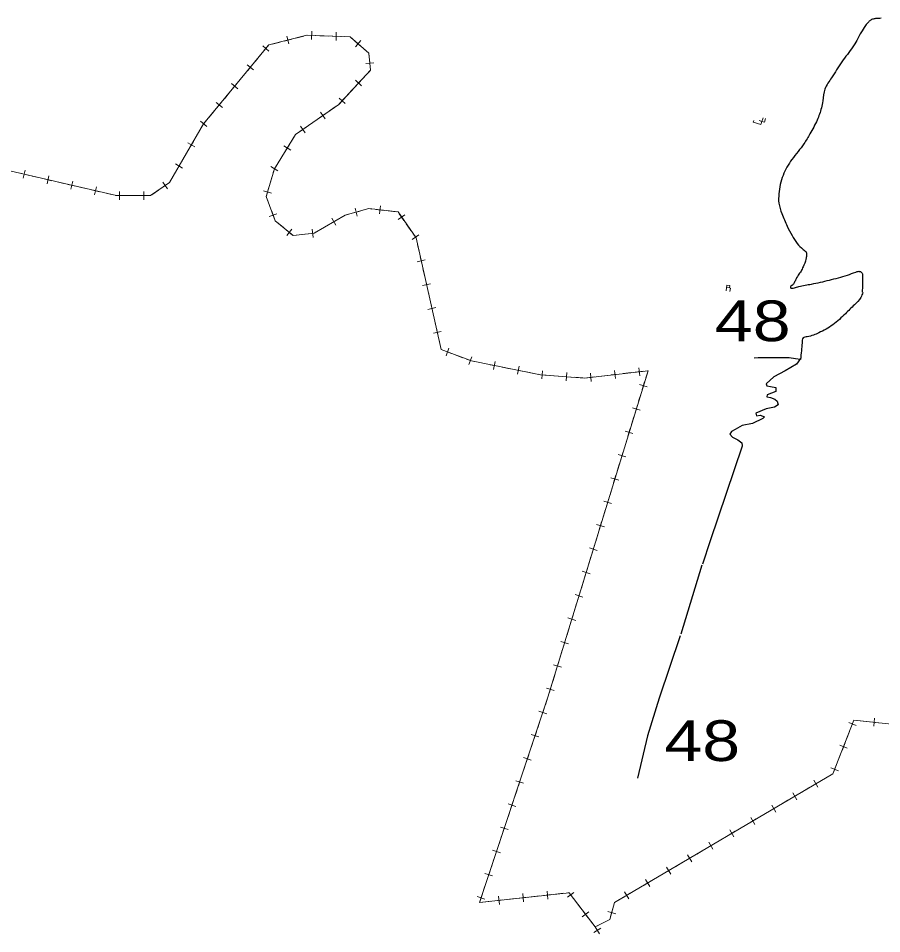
# Model space of a CAD drawing. Extents: x 476989 to 498418, y 4381813 to 4416555.
# Drawn here: x 485556 to 486617, y 4382275 to 4383399 of the extents above; entities that cross this region are included whole.
import ezdxf

# ---------------------------------------------------------------- set-up
doc = ezdxf.new("R2010")
doc.units = 0
doc.header["$LTSCALE"] = 20
doc.linetypes.add('MEDIUM_DASHED', pattern=[4.5, 3, -1.5])
for name, color, linetype, lineweight in [('13', 7, 'Continuous', 13), ('34', 7, 'Continuous', 13), ('48', 7, 'MEDIUM_DASHED', 13), ('6', 7, 'Continuous', 25)]:
    doc.layers.add(name, color=color, linetype=linetype, lineweight=lineweight)

msp = doc.modelspace()

# ---------------------------------------------------------------- linework, layer by layer
at = {"layer": '34'}
for p, q in [((485882.86, 4383370.82), (485892.55, 4383373.29)), ((485886.47, 4383376.9), (485888.94, 4383367.21)), ((485897.4, 4383374.53), (485907.09, 4383377)), ((485911.95, 4383377.96), (485921.94, 4383377.59)), ((485917.13, 4383382.77), (485916.76, 4383372.78)), ((485926.94, 4383377.4), (485936.93, 4383377.02)), ((485941.92, 4383376.83), (485951.91, 4383376.46)), ((485947.1, 4383381.64), (485946.73, 4383371.65)), ((485856.63, 4383364.92), (485864.34, 4383358.56)), ((485857.31, 4383357.88), (485863.67, 4383365.6)), ((485868.34, 4383367.11), (485878.03, 4383369.58)), ((485969.96, 4383370.82), (485977.5, 4383364.26)), ((485977.01, 4383371.31), (485970.45, 4383363.77)), ((485847.77, 4383346.32), (485854.13, 4383354.03)), ((485837.55, 4383341.78), (485845.26, 4383335.42)), ((485838.22, 4383334.75), (485844.59, 4383342.46)), ((485993.15, 4383344.13), (485983.2, 4383343.18)), ((485987.7, 4383348.63), (485988.65, 4383338.68)), ((485828.69, 4383323.18), (485835.05, 4383330.9)), ((485988.11, 4383334.04), (485981.31, 4383326.71)), ((485818.47, 4383318.65), (485826.18, 4383312.29)), ((485819.14, 4383311.61), (485825.5, 4383319.32)), ((485978.17, 4383315.99), (485970.84, 4383322.8)), ((485977.91, 4383323.06), (485971.11, 4383315.73)), ((485809.6, 4383300.05), (485815.97, 4383307.76)), ((485967.7, 4383312.07), (485960.9, 4383304.74)), ((485799.38, 4383295.51), (485807.1, 4383289.15)), ((485800.06, 4383288.47), (485806.42, 4383296.19)), ((485957.76, 4383294.01), (485950.44, 4383300.82)), ((485957.5, 4383301.08), (485950.7, 4383293.75)), ((485790.52, 4383276.91), (485796.89, 4383284.62)), ((485934.45, 4383282.15), (485926.25, 4383276.42)), ((485933.21, 4383275.18), (485927.49, 4383283.38)), ((485946.74, 4383290.73), (485938.54, 4383285)), ((485780.3, 4383272.38), (485788.02, 4383266.01)), ((485922.15, 4383273.56), (485913.95, 4383267.83)), ((485774.05, 4383251.95), (485779.09, 4383260.59)), ((485909.86, 4383264.98), (485901.66, 4383259.25)), ((485908.62, 4383258.02), (485902.9, 4383266.22)), ((485764.7, 4383245.83), (485773.33, 4383240.79)), ((485766.5, 4383238.99), (485771.54, 4383247.63)), ((485891.09, 4383236.95), (485882.59, 4383242.22)), ((485889.47, 4383243.84), (485884.21, 4383235.33)), ((485758.94, 4383226.05), (485763.98, 4383234.68)), ((485881.57, 4383231.08), (485876.31, 4383222.58)), ((485749.59, 4383219.93), (485758.22, 4383214.89)), ((485751.39, 4383213.09), (485756.42, 4383221.73)), ((485875.3, 4383211.45), (485866.8, 4383216.72)), ((485558.85, 4383208.39), (485568.59, 4383206.13)), ((485564.85, 4383212.13), (485562.59, 4383202.39)), ((485573.46, 4383205), (485583.2, 4383202.74)), ((485594.06, 4383205.36), (485591.8, 4383195.61)), ((485743.83, 4383200.14), (485748.87, 4383208.78)), ((485868.21, 4383204.5), (485865.39, 4383194.91)), ((485588.06, 4383201.61), (485597.8, 4383199.36)), ((485602.67, 4383198.23), (485612.42, 4383195.97)), ((485617.28, 4383194.84), (485627.02, 4383192.58)), ((485623.28, 4383198.58), (485621.02, 4383188.84)), ((485732.67, 4383190.51), (485740.88, 4383196.22)), ((485733.92, 4383197.47), (485739.63, 4383189.26)), ((485631.89, 4383191.46), (485641.63, 4383189.2)), ((485646.49, 4383188.07), (485656.23, 4383185.81)), ((485652.49, 4383191.81), (485650.23, 4383182.07)), ((485661.11, 4383184.68), (485670.85, 4383182.43)), ((485680.67, 4383186), (485680.67, 4383176)), ((485690.67, 4383181), (485700.67, 4383181)), ((485705.66, 4383181), (485715.66, 4383181)), ((485710.66, 4383186), (485710.66, 4383176)), ((485720.37, 4383181.95), (485728.58, 4383187.66)), ((485867.36, 4383183.91), (485857.77, 4383186.74)), ((485863.98, 4383190.12), (485861.16, 4383180.53)), ((485862.53, 4383175.82), (485865.97, 4383166.43)), ((485874.11, 4383158.78), (485864.72, 4383155.33)), ((485867.69, 4383161.75), (485871.13, 4383152.36)), ((485966.62, 4383159.38), (485976.26, 4383162.04)), ((485970.11, 4383165.53), (485972.77, 4383155.89)), ((485995.79, 4383164.02), (486005.73, 4383162.92)), ((486001.31, 4383168.44), (486000.21, 4383158.5)), ((486010.7, 4383162.37), (486020.64, 4383161.26)), ((486024.48, 4383158.85), (486030.15, 4383150.61)), ((485873.92, 4383148.43), (485881.66, 4383142.09)), ((485939.78, 4383146.45), (485948.44, 4383151.46)), ((485941.6, 4383153.29), (485946.61, 4383144.63)), ((486031.43, 4383157.56), (486023.19, 4383151.89)), ((485885.53, 4383138.93), (485893.27, 4383132.6)), ((485892.56, 4383139.64), (485886.23, 4383131.9)), ((485917.31, 4383139.72), (485918.46, 4383129.79)), ((485926.81, 4383138.94), (485935.46, 4383143.95)), ((486032.98, 4383146.48), (486038.64, 4383138.24)), ((485898.02, 4383132.46), (485907.96, 4383133.61)), ((486048.42, 4383132.84), (486040.18, 4383127.18)), ((486046.94, 4383120.44), (486049.14, 4383110.69)), ((486056.22, 4383102.05), (486046.47, 4383099.84)), ((486050.24, 4383105.82), (486052.45, 4383096.07)), ((486053.55, 4383091.19), (486055.76, 4383081.44)), ((486062.84, 4383072.8), (486053.09, 4383070.59)), ((486056.86, 4383076.57), (486059.07, 4383066.82)), ((486060.17, 4383061.94), (486062.38, 4383052.19)), ((486063.48, 4383047.32), (486065.69, 4383037.57)), ((486069.46, 4383043.55), (486059.71, 4383041.34)), ((486066.79, 4383032.69), (486069, 4383022.94)), ((486076.08, 4383014.3), (486066.33, 4383012.09)), ((486070.1, 4383018.07), (486072.31, 4383008.32)), ((486073.41, 4383003.44), (486075.62, 4382993.69)), ((486079.05, 4382990.85), (486088.4, 4382987.31)), ((486085.49, 4382993.75), (486081.95, 4382984.4)), ((486093.08, 4382985.54), (486102.43, 4382982)), ((486113.54, 4382983.14), (486110, 4382973.79)), ((486121.52, 4382976.3), (486131.32, 4382974.34)), ((486136.22, 4382973.36), (486146.02, 4382971.4)), ((486142.1, 4382977.28), (486140.14, 4382967.47)), ((486150.93, 4382970.41), (486160.73, 4382968.45)), ((486165.63, 4382967.47), (486175.43, 4382965.51)), ((486171.51, 4382971.4), (486169.55, 4382961.59)), ((486318.77, 4382969.74), (486319.91, 4382959.8)), ((486180.33, 4382964.53), (486190.14, 4382962.57)), ((486200.34, 4382965.84), (486199.6, 4382955.87)), ((486209.94, 4382960.12), (486219.91, 4382959.38)), ((486224.89, 4382959.01), (486234.86, 4382958.27)), ((486230.25, 4382963.63), (486229.51, 4382953.65)), ((486239.85, 4382957.9), (486249.82, 4382957.16)), ((486254.79, 4382957.32), (486264.72, 4382958.47)), ((486259.18, 4382962.86), (486260.33, 4382952.93)), ((486269.69, 4382959.04), (486279.62, 4382960.19)), ((486284.58, 4382960.76), (486294.51, 4382961.91)), ((486288.97, 4382966.3), (486290.12, 4382956.37)), ((486299.48, 4382962.48), (486309.42, 4382963.62)), ((486314.37, 4382964.2), (486324.31, 4382965.34)), ((486329.13, 4382946.12), (486319.57, 4382949.05)), ((486325.82, 4382952.37), (486322.89, 4382942.81)), ((486321.42, 4382938.03), (486318.49, 4382928.47)), ((486317.02, 4382923.7), (486314.09, 4382914.14)), ((486320.34, 4382917.45), (486310.78, 4382920.38)), ((486312.63, 4382909.36), (486309.69, 4382899.8)), ((486311.54, 4382888.78), (486301.98, 4382891.71)), ((486308.23, 4382895.02), (486305.3, 4382885.46)), ((486303.83, 4382880.68), (486300.9, 4382871.12)), ((486299.44, 4382866.35), (486296.5, 4382856.79)), ((486302.75, 4382860.11), (486293.19, 4382863.04)), ((486295.04, 4382852.01), (486292.1, 4382842.45)), ((486293.95, 4382831.44), (486284.39, 4382834.37)), ((486290.64, 4382837.68), (486287.71, 4382828.12)), ((486286.24, 4382823.34), (486283.31, 4382813.78)), ((486285.16, 4382802.76), (486275.6, 4382805.7)), ((486281.85, 4382809.01), (486278.91, 4382799.45)), ((486277.45, 4382794.67), (486274.51, 4382785.11)), ((486276.37, 4382774.09), (486266.81, 4382777.02)), ((486273.05, 4382780.34), (486270.12, 4382770.78)), ((486268.65, 4382766), (486265.72, 4382756.44)), ((486267.57, 4382745.42), (486258.01, 4382748.35)), ((486264.26, 4382751.67), (486261.32, 4382742.11)), ((486259.86, 4382737.33), (486256.93, 4382727.77)), ((486255.46, 4382723), (486252.53, 4382713.44)), ((486251.06, 4382708.65), (486248.13, 4382699.09)), ((486258.78, 4382716.75), (486249.22, 4382719.68)), ((486249.98, 4382688.08), (486240.42, 4382691.01)), ((486246.67, 4382694.32), (486243.74, 4382684.76)), ((486242.27, 4382679.98), (486239.34, 4382670.42)), ((486237.87, 4382665.65), (486234.94, 4382656.09)), ((486241.19, 4382659.41), (486231.63, 4382662.34)), ((486233.47, 4382651.31), (486230.54, 4382641.75)), ((486232.39, 4382630.73), (486222.83, 4382633.67)), ((486229.08, 4382636.98), (486226.15, 4382627.42)), ((486224.68, 4382622.64), (486221.75, 4382613.08)), ((486220.28, 4382608.31), (486217.35, 4382598.75)), ((486223.6, 4382602.06), (486214.04, 4382605)), ((486215.89, 4382593.97), (486212.95, 4382584.41)), ((486214.8, 4382573.39), (486205.24, 4382576.32)), ((486211.49, 4382579.64), (486208.56, 4382570.08)), ((486205.52, 4382544.75), (486196.03, 4382547.91)), ((486202.36, 4382551.07), (486199.2, 4382541.59)), ((486197.61, 4382536.84), (486194.45, 4382527.36)), ((486585.8, 4382530.46), (486576.49, 4382534.13)), ((486582.98, 4382536.94), (486579.31, 4382527.64)), ((486597.84, 4382535.39), (486587.9, 4382536.47)), ((486612.76, 4382533.77), (486602.81, 4382534.85)), ((486607.24, 4382529.34), (486608.33, 4382539.28)), ((486196.04, 4382516.3), (486186.55, 4382519.46)), ((486192.87, 4382522.62), (486189.71, 4382513.14)), ((486577.48, 4382522.99), (486573.82, 4382513.68)), ((486188.13, 4382508.39), (486184.97, 4382498.91)), ((486574.81, 4382502.56), (486565.5, 4382506.22)), ((486571.99, 4382509.04), (486568.32, 4382499.74)), ((486566.49, 4382495.09), (486562.82, 4382485.78)), ((486186.55, 4382487.85), (486177.07, 4382491.01)), ((486183.39, 4382494.17), (486180.23, 4382484.69)), ((486178.65, 4382479.94), (486175.49, 4382470.46)), ((486563.81, 4382474.65), (486554.51, 4382478.32)), ((486560.99, 4382481.14), (486557.33, 4382471.83)), ((486177.07, 4382459.4), (486167.58, 4382462.56)), ((486173.91, 4382465.72), (486170.74, 4382456.23)), ((486540.55, 4382461.3), (486531.94, 4382456.22)), ((486538.79, 4382454.46), (486533.71, 4382463.07)), ((486553.47, 4382468.92), (486544.85, 4382463.84)), ((486169.16, 4382451.49), (486166, 4382442)), ((486527.63, 4382453.69), (486519.02, 4382448.61)), ((486514.72, 4382446.07), (486506.1, 4382440.99)), ((486512.95, 4382439.23), (486507.87, 4382447.84)), ((486167.59, 4382430.95), (486158.1, 4382434.11)), ((486164.42, 4382437.27), (486161.26, 4382427.78)), ((486488.88, 4382430.84), (486480.27, 4382425.76)), ((486487.12, 4382424), (486482.04, 4382432.61)), ((486501.8, 4382438.45), (486493.18, 4382433.38)), ((486159.68, 4382423.04), (486156.52, 4382413.55)), ((486461.28, 4382408.76), (486456.2, 4382417.38)), ((486475.96, 4382423.22), (486467.35, 4382418.15)), ((486158.1, 4382402.49), (486148.62, 4382405.66)), ((486154.94, 4382408.82), (486151.78, 4382399.33)), ((486450.13, 4382407.99), (486441.51, 4382402.91)), ((486463.05, 4382415.61), (486454.43, 4382410.53)), ((486150.2, 4382394.59), (486147.03, 4382385.1)), ((486437.21, 4382400.38), (486428.6, 4382395.3)), ((486435.45, 4382393.53), (486430.37, 4382402.15)), ((486411.38, 4382385.15), (486402.77, 4382380.07)), ((486409.61, 4382378.3), (486404.53, 4382386.92)), ((486424.29, 4382392.76), (486415.68, 4382387.68)), ((486148.62, 4382374.04), (486139.13, 4382377.21)), ((486145.46, 4382380.37), (486142.29, 4382370.88)), ((486383.78, 4382363.07), (486378.7, 4382371.69)), ((486398.46, 4382377.53), (486389.84, 4382372.45)), ((486140.71, 4382366.14), (486137.55, 4382356.65)), ((486372.62, 4382362.3), (486364.01, 4382357.22)), ((486385.55, 4382369.92), (486376.93, 4382364.84)), ((486135.97, 4382351.92), (486132.81, 4382342.43)), ((486359.71, 4382354.69), (486351.1, 4382349.61)), ((486357.94, 4382347.84), (486352.86, 4382356.46)), ((486131.23, 4382337.69), (486128.07, 4382328.2)), ((486139.13, 4382345.59), (486129.65, 4382348.75)), ((486333.88, 4382339.46), (486325.26, 4382334.38)), ((486332.11, 4382332.61), (486327.03, 4382341.23)), ((486346.79, 4382347.07), (486338.18, 4382341.99)), ((486205.9, 4382327.07), (486206.98, 4382317.13)), ((486320.96, 4382331.84), (486312.34, 4382326.76)), ((486129.65, 4382317.14), (486120.16, 4382320.3)), ((486126.49, 4382323.47), (486123.33, 4382313.98)), ((486141.85, 4382315.06), (486151.79, 4382316.14)), ((486146.27, 4382320.57), (486147.36, 4382310.63)), ((486156.76, 4382316.68), (486166.7, 4382317.77)), ((486171.66, 4382318.31), (486181.6, 4382319.39)), ((486176.09, 4382323.82), (486177.17, 4382313.88)), ((486186.57, 4382319.93), (486196.51, 4382321.02)), ((486201.47, 4382321.56), (486211.41, 4382322.65)), ((486216.38, 4382323.19), (486226.32, 4382324.27)), ((486238.96, 4382325.43), (486231.01, 4382319.36)), ((486308.04, 4382324.23), (486299.43, 4382319.15)), ((486306.27, 4382317.38), (486301.2, 4382325.99)), ((486126.94, 4382313.43), (486136.89, 4382314.51)), ((486241.05, 4382314.44), (486247.11, 4382306.49)), ((486286.83, 4382305.42), (486284.09, 4382295.8)), ((486257.14, 4382301.57), (486249.18, 4382295.51)), ((486250.13, 4382302.52), (486256.19, 4382294.56)), ((486290.27, 4382299.24), (486280.65, 4382301.98)), ((486259.22, 4382290.59), (486265, 4382283)), ((486271.92, 4382281.59), (486263.58, 4382276.08)), ((486268.66, 4382284.83), (486265, 4382283)), ((486265, 4382283), (486270.51, 4382274.66)), ((486282.07, 4382291.53), (486273.12, 4382287.06))]:
    msp.add_line(p, q, dxfattribs=at)
for points in [[(485526, 4383216), (485677, 4383181), (485719, 4383181), (485742, 4383197), (485784, 4383269), (485864, 4383366), (485911, 4383378), (485964, 4383376), (485987, 4383356), (485989, 4383335), (485950, 4383293), (485897, 4383256), (485871, 4383214), (485861, 4383180), (485872, 4383150), (485894, 4383132), (485920, 4383135), (485958, 4383157), (485987, 4383165), (486023, 4383161), (486045, 4383129), (486076, 4382992), (486113, 4382978), (486198, 4382961), (486252, 4382957), (486330, 4382966), (486207, 4382565), (486123, 4382313), (486233, 4382325), (486265, 4382283)], [(485956.91, 4383376.27), (485964, 4383376), (485966.19, 4383374.1)], [(485981.27, 4383360.98), (485987, 4383356), (485987.23, 4383353.6)], [(487676.62, 4383311.4), (487577, 4383232), (487304, 4383028), (487077, 4382869), (487054, 4382844), (487031, 4382851), (487023, 4382817), (486778, 4382653), (486740, 4382634), (486629, 4382532), (486583, 4382537), (486557, 4382471), (486289, 4382313), (486283, 4382292), (486265, 4382283)], [(485781.61, 4383264.9), (485784, 4383269), (485787.34, 4383273.05)], [(485897.56, 4383256.39), (485897, 4383256), (485892.1, 4383248.08)], [(485873.68, 4383218.34), (485871, 4383214), (485869.62, 4383209.3)], [(485675.71, 4383181.3), (485677, 4383181), (485685.67, 4383181)], [(485981.08, 4383163.37), (485987, 4383165), (485990.83, 4383164.57)], [(485952.76, 4383153.97), (485958, 4383157), (485961.81, 4383158.05)], [(485912.92, 4383134.18), (485920, 4383135), (485922.48, 4383136.44)], [(486041.47, 4383134.13), (486045, 4383129), (486045.83, 4383125.32)], [(486107.1, 4382980.23), (486113, 4382978), (486116.62, 4382977.28)], [(486195.03, 4382961.59), (486198, 4382961), (486204.96, 4382960.48)], [(486329.27, 4382965.92), (486330, 4382966), (486327.28, 4382957.14)], [(486207.09, 4382565.3), (486207, 4382565), (486203.94, 4382555.81)], [(486231.29, 4382324.81), (486233, 4382325), (486238.02, 4382318.42)], [(486295.12, 4382316.61), (486289, 4382313), (486288.2, 4382310.22)]]:
    msp.add_lwpolyline(points, dxfattribs=at)
at = {"layer": '48'}
msp.add_line((486429.89, 4383067.74), (486426.6, 4383068.42), dxfattribs=at)
for points in [[(486474.49, 4383275.89), (486473.11, 4383271.21), (486469.61, 4383272.22), (486468.54, 4383268.53), (486459.21, 4383271.2), (486459.85, 4383273.46)], [(486471.29, 4383276.64), (486469.61, 4383272.22), (486466.47, 4383273.39)], [(486426.03, 4383064.26), (486426.95, 4383071), (486430.31, 4383070.49), (486429.89, 4383067.74), (486431.31, 4383067.49), (486430.58, 4383063.35)]]:
    msp.add_lwpolyline(points, dxfattribs=at)
at = {"layer": '6'}
msp.add_line((486396.11, 4382727.09), (486370.16, 4382642.32), dxfattribs=at)
for points in [[(486517.39, 4382981.15), (486512.54, 4382973.9), (486498.53, 4382965.91), (486484.52, 4382958.57), (486475.19, 4382949.91), (486475.85, 4382947.24), (486480.52, 4382946.58), (486487.19, 4382945.24), (486487.19, 4382940.58), (486476.52, 4382936.58), (486475.85, 4382933.91), (486480.52, 4382933.24), (486485.86, 4382931.24), (486488.53, 4382928.58), (486489.86, 4382923.91), (486485.19, 4382921.25), (486475.19, 4382919.25), (486462.51, 4382913.91), (486463.18, 4382910.58), (486467.85, 4382911.25), (486473.18, 4382909.25), (486471.18, 4382907.25), (486458.51, 4382901.25), (486445.84, 4382898.58), (486437.16, 4382893.92), (486432.49, 4382891.25), (486430.49, 4382887.92), (486433.83, 4382884.59), (486440.5, 4382881.25), (486445.17, 4382877.25), (486445.84, 4382873.92)], [(486517.24, 4382979.78), (486511.21, 4382980.64), (486503.53, 4382981.64), (486492.53, 4382981.64), (486482.86, 4382981.97), (486465.18, 4382981.64), (486460.51, 4382981.31)], [(486445.81, 4382873.41), (486406.24, 4382757.15), (486396.79, 4382728.38)], [(486369.4, 4382640.61), (486343.6, 4382563.91), (486329.34, 4382517.49), (486317.11, 4382465.75)]]:
    msp.add_lwpolyline(points, dxfattribs=at)
for points in [[(486616.4, 4383398.76), (486609.53, 4383398.32), (486605.76, 4383397.51), (486603.64, 4383396.68), (486601.06, 4383394.53), (486581.77, 4383363.75), (486567.92, 4383345.34), (486555.49, 4383325.84), (486547.31, 4383311.93), (486544.63, 4383297.26), (486542.93, 4383288.69), (486537.77, 4383273.81), (486528.83, 4383256.87), (486521.61, 4383244.78), (486506.85, 4383225.48), (486495.82, 4383205.81), (486490.76, 4383183.12), (486490.75, 4383171.7), (486494.48, 4383158.89), (486500.87, 4383143.53), (486507.02, 4383132), (486513.34, 4383122.31), (486520.6, 4383114.98), (486524.69, 4383110.49), (486524.72, 4383107.37), (486523.98, 4383102.8), (486520.48, 4383093.44), (486518.01, 4383088.42), (486514.34, 4383083.16), (486511.09, 4383077.17), (486509.02, 4383072.98), (486506.76, 4383070.57), (486504.86, 4383068.89), (486504.98, 4383068.05), (486506.45, 4383067.29), (486509.87, 4383067.88), (486515.23, 4383069.39), (486530.79, 4383072.38), (486552.79, 4383077.34), (486574.89, 4383083.42), (486585.15, 4383087.17), (486588.99, 4383088.06), (486590.1, 4383087.94), (486592.93, 4383085.95), (486593.37, 4383080.97), (486593.38, 4383076.71), (486593.42, 4383068.62), (486592.95, 4383062.34)], [(486593.85, 4383062.23), (486591.36, 4383055.96), (486583.58, 4383046.92), (486572.39, 4383036.05), (486557.19, 4383022.53), (486539.86, 4383012.5), (486525.54, 4383007.75), (486520.42, 4383006.25), (486519.2, 4383000.04), (486518.39, 4382990.6), (486517.24, 4382979.78)]]:
    msp.add_spline(points, degree=3, dxfattribs=at)

# ---------------------------------------------------------------- texts
at = {"layer": '13', "width": 1.25}
for p in [(486412.2, 4383002.28), (486350.15, 4382486.73)]:
    msp.add_text('48', height=50, dxfattribs=at).set_placement(p)

doc.saveas('drawing.dxf')
